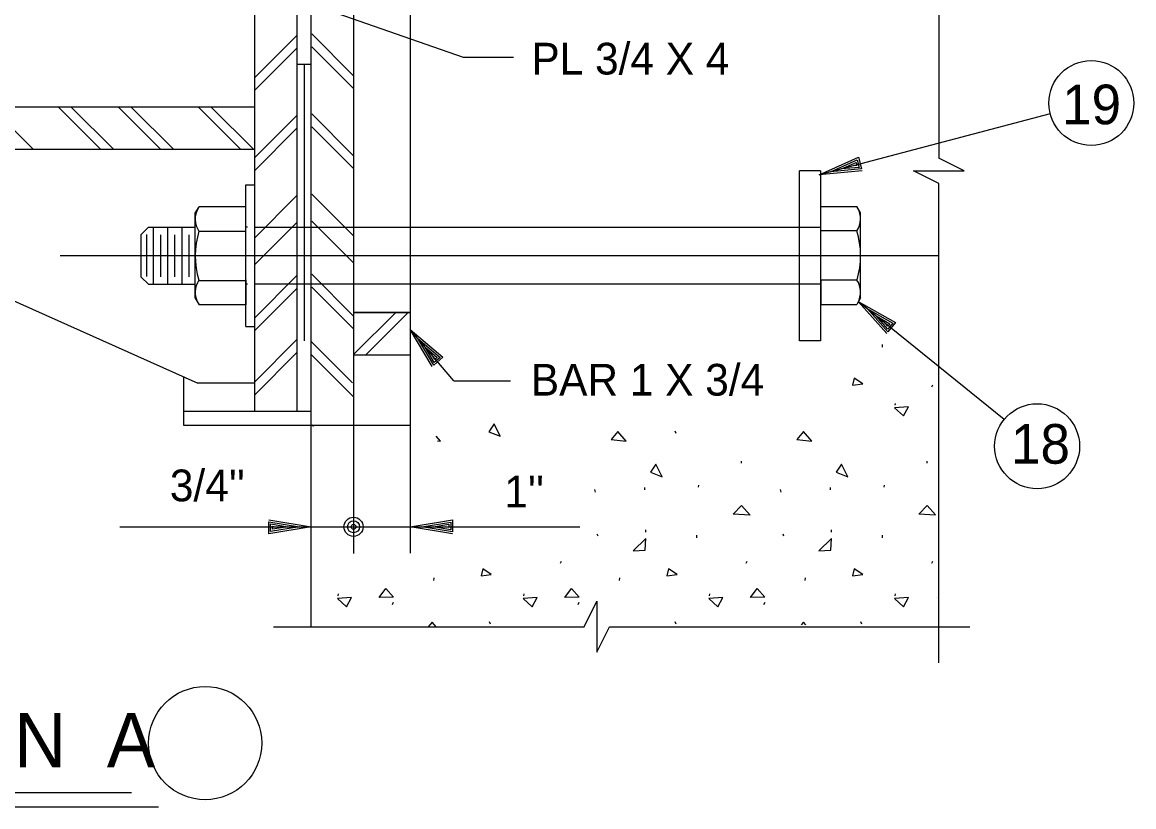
# Model space of a CAD drawing. Extents: x 0.1 to 13.5, y 0.1 to 9.5.
# Drawn here: x 8.756 to 10.392, y 5.682 to 6.836 of the extents above; entities that cross this region are included whole.
import ezdxf

# ---------------------------------------------------------------- set-up
doc = ezdxf.new("R2010")
doc.units = 0
for name, color, linetype in [('Level 10', 7, 'Continuous'), ('Level 13', 7, 'Continuous'), ('Level 2', 7, 'Continuous'), ('Level 25', 7, 'Continuous'), ('Level 3', 7, 'Continuous'), ('Level 50', 7, 'Continuous'), ('Level 6', 7, 'Continuous')]:
    doc.layers.add(name, color=color, linetype=linetype)

msp = doc.modelspace()

# ---------------------------------------------------------------- linework, layer by layer
at = {"layer": 'Level 10'}
for p, q in [((10.0221, 6.3583), (10.0221, 6.362)), ((10.0947, 6.3), (10.0961, 6.3029)), ((10.0407, 6.2728), (10.0409, 6.2755)), ((9.7184, 6.231), (9.7167, 6.2344)), ((9.8147, 6.1875), (9.8144, 6.1905)), ((10.088, 6.1875), (10.0877, 6.1905)), ((9.7511, 6.1524), (9.7516, 6.1552)), ((10.0244, 6.1524), (10.0249, 6.1552)), ((9.5996, 6.145), (9.5985, 6.1487)), ((9.6723, 6.148), (9.6723, 6.1517)), ((9.8729, 6.145), (9.8718, 6.1487)), ((9.9456, 6.148), (9.9456, 6.1517)), ((9.6736, 6.0858), (9.6736, 6.0893)), ((9.9469, 6.0858), (9.9469, 6.0893)), ((9.6033, 6.0803), (9.6022, 6.083)), ((9.7488, 6.0777), (9.7488, 6.0815)), ((9.8766, 6.0803), (9.8756, 6.083)), ((10.0221, 6.0777), (10.0221, 6.0815)), ((9.5481, 6.0402), (9.5494, 6.0432)), ((9.8214, 6.0402), (9.8227, 6.0432)), ((10.0947, 6.0402), (10.0961, 6.0432)), ((9.3615, 6.015), (9.3621, 6.0187)), ((9.6348, 6.015), (9.6354, 6.0187)), ((9.9081, 6.015), (9.9087, 6.0187)), ((9.2207, 5.9922), (9.221, 5.995)), ((9.4941, 5.9922), (9.4943, 5.995)), ((9.7674, 5.9922), (9.7676, 5.995)), ((10.0407, 5.9922), (10.0409, 5.995)), ((9.3006, 5.9797), (9.3024, 5.9829)), ((9.5739, 5.9797), (9.5757, 5.9829)), ((9.8472, 5.9797), (9.8491, 5.9829)), ((9.4451, 5.9505), (9.4434, 5.9538)), ((9.7184, 5.9505), (9.7167, 5.9538)), ((9.9917, 5.9505), (9.9901, 5.9538))]:
    msp.add_line(p, q, dxfattribs=at)
for points in [[(9.9777, 6.3022), (9.9929, 6.3041), (9.9801, 6.3127)], [(10.0397, 6.2687), (10.0531, 6.2569), (10.0602, 6.2702)], [(9.4423, 6.2338), (9.4594, 6.2271), (9.4504, 6.2456)], [(9.6447, 6.2198), (9.6324, 6.234), (9.6224, 6.2222)], [(9.9181, 6.2198), (9.9057, 6.234), (9.8957, 6.2222)], [(9.6804, 6.1742), (9.6975, 6.1676), (9.6885, 6.186)], [(9.9537, 6.1742), (9.9708, 6.1676), (9.9618, 6.186)], [(9.8024, 6.1124), (9.8143, 6.1253), (9.8271, 6.111)], [(9.6727, 6.0597), (9.6736, 6.0764), (9.6551, 6.0584)], [(9.946, 6.0597), (9.9469, 6.0764), (9.9284, 6.0584)], [(9.4311, 6.0216), (9.4462, 6.0235), (9.4335, 6.0321)], [(9.7044, 6.0216), (9.7196, 6.0235), (9.7068, 6.0321)], [(9.9777, 6.0216), (9.9929, 6.0235), (9.9801, 6.0321)], [(9.2198, 5.9882), (9.2331, 5.9763), (9.2402, 5.9896)], [(9.2809, 5.9896), (9.291, 6.0029), (9.3023, 5.9901)], [(9.4931, 5.9882), (9.5064, 5.9763), (9.5136, 5.9896)], [(9.5542, 5.9896), (9.5643, 6.0029), (9.5756, 5.9901)], [(9.7664, 5.9882), (9.7797, 5.9763), (9.7869, 5.9896)], [(9.8276, 5.9896), (9.8376, 6.0029), (9.8489, 5.9901)], [(10.0397, 5.9882), (10.0531, 5.9763), (10.0602, 5.9896)]]:
    msp.add_lwpolyline(points, close=True, dxfattribs=at)
for points in [[(9.3714, 6.2198), (9.3649, 6.2273)], [(9.3669, 6.2203), (9.3714, 6.2198)], [(10.0757, 6.1124), (10.0876, 6.1253)], [(10.0876, 6.1253), (10.1, 6.1115)], [(10.1, 6.1111), (10.0757, 6.1124)], [(10.1009, 5.9896), (10.1009, 5.9897)], [(10.1009, 5.9896), (10.1009, 5.9896)], [(9.3591, 5.9535), (9.3534, 5.9467)], [(9.3649, 5.9467), (9.3591, 5.9535)], [(9.9057, 5.9535), (9.9022, 5.9494)], [(9.9092, 5.9495), (9.9057, 5.9535)]]:
    msp.add_lwpolyline(points, dxfattribs=at)
at = {"layer": 'Level 13'}
for points in [[(10.1049, 6.5989), (10.0674, 6.6175), (10.1423, 6.6175), (10.1049, 6.6363)], [(9.5827, 5.9467), (9.6014, 5.9842), (9.6014, 5.9093), (9.6201, 5.9467)]]:
    msp.add_lwpolyline(points, dxfattribs=at)
at = {"layer": 'Level 2'}
for p, q in [((9.1809, 5.9467), (9.1809, 8.0969)), ((9.0976, 7.0344), (9.0976, 6.2636)), ((9.1601, 7.0344), (9.1601, 6.2636)), ((9.2434, 7.0344), (9.2434, 6.535)), ((9.3268, 7.0344), (9.3268, 6.2427)), ((10.1049, 7.0344), (10.1049, 6.6363)), ((9.1809, 6.774), (9.1601, 6.774)), ((9.1705, 6.774), (9.1705, 6.3677)), ((9.0976, 6.7115), (8.3268, 6.7115)), ((9.0976, 6.649), (7.983, 6.649)), ((9.8997, 6.3677), (9.8997, 6.6177)), ((9.9309, 6.6177), (9.8997, 6.6177)), ((9.9312, 6.3677), (9.9312, 6.6177)), ((9.0846, 6.3886), (9.0846, 6.5969)), ((9.0846, 6.5969), (9.0976, 6.5969)), ((10.1049, 5.8938), (10.1049, 6.5989)), ((9.0104, 6.5553), (9.016, 6.5649)), ((9.0846, 6.5649), (9.016, 6.5649)), ((9.9312, 6.5654), (9.9841, 6.5654)), ((9.9897, 6.5557), (9.9841, 6.5654)), ((9.0104, 6.4302), (9.0104, 6.5553)), ((9.3268, 6.5558), (9.3268, 6.3469)), ((9.3268, 6.5484), (9.3268, 6.3469)), ((9.9897, 6.4306), (9.9897, 6.5557)), ((8.9414, 6.5346), (8.9309, 6.5241)), ((8.9414, 6.5346), (9.0104, 6.5346)), ((8.9491, 6.4509), (8.9491, 6.5346)), ((8.97, 6.4509), (8.97, 6.5346)), ((8.9909, 6.4509), (8.9909, 6.5346)), ((9.0159, 6.5289), (9.0846, 6.5289)), ((9.0872, 6.5346), (9.0846, 6.5346)), ((9.0976, 6.535), (9.3268, 6.535)), ((9.2434, 6.535), (9.2434, 6.2427)), ((9.3268, 6.535), (9.9312, 6.535)), ((9.9843, 6.5293), (9.9312, 6.5293)), ((8.9309, 6.4614), (8.9309, 6.5241)), ((8.9309, 6.4614), (8.9309, 6.5241)), ((8.9392, 6.462), (8.9392, 6.5242)), ((8.9595, 6.4615), (8.9595, 6.5237)), ((8.9804, 6.4615), (8.9804, 6.5237)), ((9.0013, 6.4615), (9.0013, 6.5237)), ((10.1049, 6.4927), (8.8116, 6.4927)), ((8.9414, 6.4509), (8.9309, 6.4614)), ((8.9414, 6.4509), (9.0104, 6.4509)), ((9.0159, 6.4565), (9.0846, 6.4565)), ((9.0846, 6.4571), (9.0846, 6.4205)), ((9.0872, 6.4509), (9.0846, 6.4509)), ((9.0976, 6.4513), (9.9312, 6.4513)), ((9.9312, 6.4574), (9.9312, 6.4209)), ((9.9843, 6.4569), (9.9312, 6.4569)), ((9.9897, 6.4306), (9.9841, 6.4209)), ((9.0104, 6.4302), (9.016, 6.4205)), ((9.0846, 6.4205), (9.016, 6.4205)), ((9.9312, 6.4209), (9.9841, 6.4209)), ((9.2434, 6.4094), (9.3268, 6.4094)), ((9.2434, 6.4094), (9.2434, 6.3469)), ((9.3268, 6.4094), (9.2434, 6.4094)), ((9.3268, 6.4094), (9.3268, 6.3469)), ((9.0846, 6.3886), (9.0976, 6.3886)), ((9.9309, 6.3677), (9.8997, 6.3677)), ((9.2434, 6.3469), (9.3268, 6.3469)), ((8.9934, 6.2427), (8.9934, 6.3145)), ((9.0976, 6.3052), (9.0143, 6.3052)), ((9.1809, 6.2636), (8.9934, 6.2636)), ((9.2434, 6.2427), (8.9934, 6.2427)), ((9.3268, 6.2427), (9.2434, 6.2427)), ((9.3268, 6.2427), (9.2434, 6.2427)), ((9.1256, 5.9467), (9.5827, 5.9467)), ((9.6201, 5.9467), (10.1506, 5.9467))]:
    msp.add_line(p, q, dxfattribs=at)
for points in [[(9.0976, 6.7545), (9.1601, 6.817)], [(9.2434, 6.7576), (9.1819, 6.8191)], [(9.0976, 6.7357), (9.1601, 6.7982)], [(9.2434, 6.7387), (9.1819, 6.8003)], [(8.7725, 6.649), (8.71, 6.7115)], [(8.8715, 6.649), (8.809, 6.7115)], [(8.8904, 6.649), (8.8279, 6.7115)], [(8.9598, 6.649), (8.8973, 6.7115)], [(8.9787, 6.649), (8.9161, 6.7115)], [(9.0776, 6.649), (9.0151, 6.7115)], [(9.0965, 6.649), (9.034, 6.7115)], [(9.0976, 6.6367), (9.1601, 6.6992)], [(9.2434, 6.6397), (9.1819, 6.7013)], [(9.0976, 6.6178), (9.1601, 6.6803)], [(9.2434, 6.6209), (9.1819, 6.6824)], [(9.0976, 6.5188), (9.1601, 6.5813)], [(9.2434, 6.5219), (9.1819, 6.5834)], [(9.0976, 6.4791), (9.1601, 6.5416)], [(9.2434, 6.4822), (9.1819, 6.5437)], [(9.0976, 6.401), (9.1601, 6.4635)], [(9.2434, 6.404), (9.1819, 6.4656)], [(9.2434, 6.3852), (9.1819, 6.4467)], [(9.0976, 6.3821), (9.1601, 6.4446)], [(9.2434, 6.3474), (9.3054, 6.4094)], [(9.2615, 6.3469), (9.324, 6.4094)], [(9.0976, 6.3069), (9.1601, 6.3694)], [(9.242, 6.3057), (9.1805, 6.3672)], [(9.0976, 6.2876), (9.1601, 6.3501)], [(9.2427, 6.2856), (9.1812, 6.3472)], [(9.1842, 6.2412), (9.1819, 6.2436)]]:
    msp.add_lwpolyline(points, dxfattribs=at)
for centre, radius, start, end in [((9.0417, 6.5467), 0.0314, 149.7124, 214.511), ((9.9584, 6.5471), 0.0314, 325.489, 30.2876), ((9.1359, 6.4923), 0.1255, 163.0184, 196.4966), ((9.8643, 6.4927), 0.1255, 343.5034, 16.9816), ((9.0417, 6.4388), 0.0314, 145.489, 210.2876), ((9.9584, 6.4392), 0.0314, 329.7124, 34.511)]:
    msp.add_arc(centre, radius, start, end, dxfattribs=at)
at = {"layer": 'Level 25'}
for p, q in [((8.4309, 6.5656), (9.0143, 6.3052)), ((9.3909, 6.3086), (9.3268, 6.3841))]:
    msp.add_line(p, q, dxfattribs=at)
at = {"layer": 'Level 3'}
for p, q in [((8.8977, 6.962), (9.4046, 6.7848)), ((9.4046, 6.7848), (9.4789, 6.7848)), ((10.2689, 6.7015), (9.929, 6.6117)), ((9.929, 6.6117), (9.929, 6.6117)), ((9.9457, 6.6161), (9.9457, 6.6161)), ((10.201, 6.2517), (9.9863, 6.4255)), ((9.9863, 6.4255), (9.9863, 6.4255)), ((9.9997, 6.4146), (9.9997, 6.4146)), ((9.2434, 6.3469), (9.2434, 6.0544)), ((9.3268, 6.3469), (9.3268, 6.0548)), ((9.3909, 6.3086), (9.4745, 6.3086)), ((8.8996, 6.0938), (9.1809, 6.0938)), ((9.1636, 6.0938), (9.1636, 6.0938)), ((9.1809, 6.0938), (9.2434, 6.0938)), ((9.1809, 6.0938), (9.1809, 6.0938)), ((9.2434, 6.0938), (9.3268, 6.0938)), ((9.3268, 6.0938), (9.5763, 6.0938)), ((9.3268, 6.0938), (9.3268, 6.0938)), ((9.3441, 6.0938), (9.3441, 6.0938)), ((8.2917, 5.7027), (8.9163, 5.7027)), ((8.2312, 5.6819), (8.9561, 5.6819))]:
    msp.add_line(p, q, dxfattribs=at)
for points in [[(9.9919, 6.6176), (9.929, 6.6117), (9.9866, 6.6376), (9.9911, 6.6205), (9.9457, 6.6161), (9.9849, 6.6337), (9.9878, 6.6227), (9.9618, 6.6204), (9.9831, 6.6298), (9.9843, 6.6253), (9.9786, 6.6248)], [(10.0282, 6.3783), (9.9863, 6.4255), (10.0412, 6.3943), (10.0301, 6.3806), (9.9997, 6.4146), (10.037, 6.3934), (10.0299, 6.3846), (10.0127, 6.4041), (10.0329, 6.3925), (10.0299, 6.3889), (10.0262, 6.3932)], [(9.1186, 6.1042), (9.1809, 6.0938), (9.1186, 6.0835), (9.1186, 6.1012), (9.1636, 6.0938), (9.1213, 6.0868), (9.1213, 6.0982), (9.1469, 6.0938), (9.1239, 6.0902), (9.1239, 6.0948), (9.1296, 6.0938)], [(9.3891, 6.0835), (9.3268, 6.0938), (9.3891, 6.1042), (9.3891, 6.0865), (9.3441, 6.0938), (9.3864, 6.1008), (9.3864, 6.0895), (9.3608, 6.0938), (9.3838, 6.0975), (9.3838, 6.0928), (9.3781, 6.0938)]]:
    msp.add_lwpolyline(points, dxfattribs=at)
for centre, radius in [((10.3294, 6.7174), 0.0625), ((10.2496, 6.2124), 0.0625), ((9.025, 5.7756), 0.0833)]:
    msp.add_circle(centre, radius, dxfattribs=at)
at = {"layer": 'Level 50'}
for p, q in [((9.3268, 6.3841), (9.3268, 6.3841)), ((9.338, 6.3709), (9.338, 6.3709))]:
    msp.add_line(p, q, dxfattribs=at)
msp.add_lwpolyline([(9.3593, 6.3299), (9.3268, 6.3841), (9.375, 6.3433), (9.3616, 6.3318), (9.338, 6.3709), (9.3707, 6.3432), (9.3621, 6.3358), (9.3488, 6.3582), (9.3665, 6.343), (9.3629, 6.34), (9.36, 6.345)], dxfattribs=at)
at = {"layer": 'Level 6'}
for radius in [0.0141, 0.00879, 0.00352]:
    msp.add_circle((9.2434, 6.0938), radius, dxfattribs=at)

# ---------------------------------------------------------------- texts
at = {"layer": 'Level 3'}
for s, height, p in [('PL 3/4 X 4', 0.04667, (9.5052, 6.7594)), ('19', 0.05833, (10.2864, 6.6862)), ('BAR 1 X 3/4', 0.046667, (9.5044, 6.2869)), ('18', 0.05833, (10.2112, 6.1867)), ("3/4''", 0.04667, (8.973, 6.1314)), ("1''", 0.04667, (9.4653, 6.1225)), ('SECTION  A', 0.08, (8.3452, 5.7398))]:
    msp.add_text(s, height=height, dxfattribs=at).set_placement(p)

doc.saveas('drawing.dxf')
